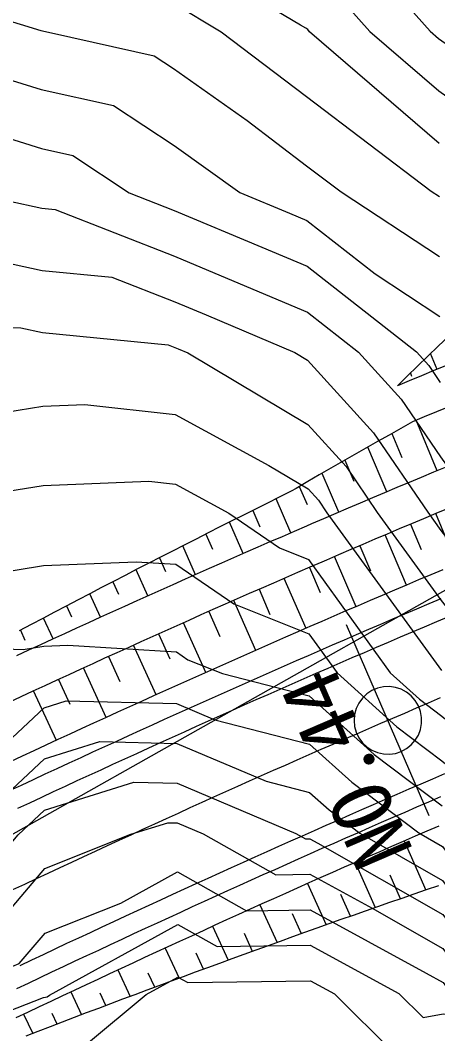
# Model space of a CAD drawing. Extents: x 42655 to 43811, y -141820 to -141156.
# Drawn here: x 43198.76 to 43214.79, y -141383.82 to -141344.87 of the extents above; entities that cross this region are included whole.
import ezdxf

# ---------------------------------------------------------------- set-up
doc = ezdxf.new("R2010")
doc.units = 0
for name, color, linetype in [('D-BMK-HTXT_1', 7, 'Continuous'), ('D-BMK_1', 7, 'Continuous'), ('D-STR-STR5_1', 7, 'Continuous'), ('D-STR_1', 7, 'Continuous'), ('ZE_HICN', 7, 'Continuous'), ('ZE_LWCN', 7, 'Continuous')]:
    doc.layers.add(name, color=color, linetype=linetype)

msp = doc.modelspace()

# ---------------------------------------------------------------- linework, layer by layer
at = {"layer": 'D-BMK-HTXT_1'}
for p, q in [((43274.802, -141333.044), (43130.975, -141414.265)), ((43214.46, -141375.449), (43211.289, -141368.104))]:
    msp.add_line(p, q, dxfattribs=at)
msp.add_lwpolyline([(43211.575, -141371.776), (43211.595, -141372.008), (43211.657, -141372.233), (43211.759, -141372.443), (43211.896, -141372.632), (43212.064, -141372.793), (43212.259, -141372.921), (43212.473, -141373.013), (43212.7, -141373.065), (43212.933, -141373.075), (43213.164, -141373.044), (43213.385, -141372.972), (43213.591, -141372.861), (43213.773, -141372.716), (43213.926, -141372.54), (43214.046, -141372.34), (43214.128, -141372.122), (43214.169, -141371.893), (43214.169, -141371.66), (43214.128, -141371.43), (43214.046, -141371.212), (43213.926, -141371.012), (43213.773, -141370.837), (43213.591, -141370.691), (43213.385, -141370.581), (43213.164, -141370.509), (43212.933, -141370.478), (43212.7, -141370.488), (43212.473, -141370.54), (43212.259, -141370.632), (43212.064, -141370.76), (43211.896, -141370.921), (43211.759, -141371.11), (43211.657, -141371.319), (43211.595, -141371.544), (43211.575, -141371.776)], dxfattribs=at)
at = {"layer": 'D-BMK_1'}
msp.add_lwpolyline([(43214.886, -141370.914), (43214.426, -141371.11), (43213.966, -141371.307), (43213.507, -141371.504), (43213.048, -141371.702), (43212.589, -141371.9), (43212.13, -141372.099), (43211.671, -141372.298), (43211.213, -141372.498), (43210.755, -141372.698), (43210.297, -141372.899), (43209.839, -141373.1), (43209.382, -141373.302), (43208.925, -141373.505), (43208.468, -141373.707), (43208.011, -141373.911), (43207.554, -141374.115), (43207.098, -141374.319), (43206.642, -141374.524), (43206.186, -141374.729), (43205.73, -141374.935), (43205.275, -141375.141), (43204.82, -141375.348), (43204.365, -141375.556), (43203.91, -141375.763), (43203.455, -141375.971), (43203.001, -141376.18), (43202.547, -141376.389), (43202.093, -141376.599), (43201.639, -141376.809), (43201.185, -141377.019), (43200.732, -141377.23), (43200.279, -141377.442), (43199.826, -141377.654), (43199.373, -141377.866), (43198.921, -141378.079), (43198.469, -141378.292)], dxfattribs=at)
at = {"layer": 'D-STR-STR5_1'}
for p, q in [((43214.761, -141358.286), (43214.511, -141357.68)), ((43213.738, -141358.431), (43213.787, -141358.55)), ((43214.765, -141362.181), (43213.958, -141360.243)), ((43213.026, -141360.749), (43213.411, -141361.668)), ((43212.829, -141362.994), (43212.103, -141361.275)), ((43211.225, -141361.777), (43211.567, -141362.581)), ((43210.989, -141363.777), (43210.349, -141362.281)), ((43209.474, -141362.787), (43209.772, -141363.479)), ((43209.152, -141364.568), (43208.583, -141363.257)), ((43207.685, -141363.707), (43207.96, -141364.337)), ((43215.526, -141365.765), (43214.715, -141363.828)), ((43207.319, -141365.367), (43206.788, -141364.158)), ((43213.743, -141364.236), (43214.15, -141365.204)), ((43205.892, -141364.612), (43206.148, -141365.191)), ((43213.591, -141366.581), (43212.771, -141364.648)), ((43205.489, -141366.175), (43204.997, -141365.068)), ((43211.8, -141365.061), (43212.213, -141366.027)), ((43204.104, -141365.525), (43204.339, -141366.054)), ((43211.66, -141367.406), (43210.83, -141365.477)), ((43209.862, -141365.895), (43210.279, -141366.859)), ((43203.663, -141366.99), (43203.211, -141365.985)), ((43209.733, -141368.241), (43208.894, -141366.316)), ((43202.32, -141366.446), (43202.535, -141366.924)), ((43201.84, -141367.814), (43201.429, -141366.909)), ((43207.928, -141366.738), (43208.349, -141367.7)), ((43200.54, -141367.374), (43200.735, -141367.801)), ((43207.81, -141369.084), (43206.962, -141367.163)), ((43200.021, -141368.644), (43199.652, -141367.841)), ((43205.998, -141367.59), (43206.424, -141368.55)), ((43205.891, -141369.937), (43205.034, -141368.02)), ((43198.765, -141368.309), (43198.938, -141368.686)), ((43204.072, -141368.451), (43204.502, -141369.409)), ((43203.976, -141370.798), (43203.11, -141368.885)), ((43202.15, -141369.32), (43202.585, -141370.276)), ((43202.064, -141371.668), (43201.191, -141369.758)), ((43200.232, -141370.198), (43200.671, -141371.152)), ((43200.157, -141372.546), (43199.275, -141370.64)), ((43213.504, -141376.407), (43214.326, -141378.296)), ((43211.617, -141377.233), (43212.384, -141378.972)), ((43213.355, -141378.633), (43212.958, -141377.726)), ((43209.789, -141378.044), (43210.5, -141379.637)), ((43211.441, -141379.303), (43211.072, -141378.471)), ((43207.964, -141378.863), (43208.618, -141380.311)), ((43209.558, -141379.973), (43209.217, -141379.213)), ((43206.143, -141379.689), (43206.738, -141380.993)), ((43207.678, -141380.651), (43207.365, -141379.963)), ((43204.325, -141380.523), (43204.861, -141381.684)), ((43205.799, -141381.338), (43205.516, -141380.721)), ((43202.511, -141381.365), (43202.985, -141382.382)), ((43203.923, -141382.032), (43203.67, -141381.488)), ((43200.7, -141382.213), (43201.112, -141383.089)), ((43202.049, -141382.735), (43201.827, -141382.261)), ((43198.892, -141383.069), (43199.241, -141383.803)), ((43200.176, -141383.445), (43199.986, -141383.042))]:
    msp.add_line(p, q, dxfattribs=at)
for points in [[(43221.944, -141353.148), (43221.489, -141353.403), (43221.035, -141353.659), (43220.581, -141353.915), (43220.127, -141354.172), (43219.673, -141354.429), (43219.22, -141354.687), (43218.768, -141354.945), (43218.316, -141355.204), (43217.864, -141355.464), (43217.413, -141355.724), (43216.962, -141355.984), (43216.511, -141356.245), (43216.061, -141356.507), (43215.611, -141356.769), (43215.209, -141357.004), (43214.811, -141357.389), (43214.413, -141357.775), (43214.016, -141358.161), (43213.619, -141358.547), (43213.242, -141358.916)], [(43215.594, -141357.943), (43215.119, -141358.138), (43214.644, -141358.334), (43214.169, -141358.531), (43213.694, -141358.728), (43213.242, -141358.916)], [(43215.216, -141359.721), (43214.743, -141359.916), (43214.27, -141360.113), (43213.82, -141360.3), (43213.371, -141360.554), (43212.923, -141360.808), (43212.475, -141361.063), (43212.027, -141361.318), (43211.58, -141361.573), (43211.134, -141361.829), (43210.688, -141362.086), (43210.242, -141362.343), (43209.797, -141362.6), (43209.352, -141362.858), (43209.164, -141362.967), (43208.706, -141363.195), (43208.249, -141363.424), (43207.792, -141363.653), (43207.336, -141363.882), (43206.88, -141364.112), (43206.424, -141364.342), (43205.969, -141364.573), (43205.513, -141364.805), (43205.059, -141365.037), (43204.604, -141365.269), (43204.15, -141365.502), (43203.696, -141365.735), (43203.243, -141365.968), (43202.79, -141366.203), (43202.337, -141366.437), (43201.884, -141366.672), (43201.432, -141366.908), (43200.98, -141367.144), (43200.529, -141367.38), (43200.078, -141367.617), (43199.627, -141367.854), (43199.176, -141368.091), (43198.726, -141368.329)], [(43215.076, -141362.052), (43214.628, -141362.239), (43214.158, -141362.435), (43213.689, -141362.632), (43213.219, -141362.829), (43212.75, -141363.027), (43212.281, -141363.226), (43211.813, -141363.425), (43211.345, -141363.624), (43210.877, -141363.824), (43210.409, -141364.025), (43209.942, -141364.226), (43209.744, -141364.312), (43209.277, -141364.513), (43208.811, -141364.716), (43208.344, -141364.919), (43207.878, -141365.122), (43207.412, -141365.326), (43206.947, -141365.531), (43206.481, -141365.736), (43206.016, -141365.941), (43205.552, -141366.147), (43205.087, -141366.354), (43204.623, -141366.561), (43204.159, -141366.768), (43203.695, -141366.976), (43203.232, -141367.184), (43202.769, -141367.393), (43202.306, -141367.602), (43201.843, -141367.812), (43201.381, -141368.022), (43200.919, -141368.233), (43200.457, -141368.444), (43199.995, -141368.656), (43199.534, -141368.868), (43199.073, -141369.081), (43198.612, -141369.294)], [(43215.184, -141363.632), (43214.716, -141363.828), (43214.248, -141364.024), (43213.78, -141364.221), (43213.313, -141364.418), (43212.846, -141364.616), (43212.379, -141364.814), (43211.912, -141365.013), (43211.446, -141365.212), (43210.98, -141365.412), (43210.514, -141365.613), (43210.339, -141365.689), (43209.874, -141365.89), (43209.408, -141366.092), (43208.944, -141366.294), (43208.479, -141366.497), (43208.015, -141366.7), (43207.551, -141366.904), (43207.087, -141367.108), (43206.623, -141367.313), (43206.16, -141367.518), (43205.697, -141367.724), (43205.234, -141367.93), (43204.772, -141368.137), (43204.31, -141368.344), (43203.848, -141368.552), (43203.386, -141368.76), (43202.924, -141368.969), (43202.463, -141369.178), (43202.002, -141369.388), (43201.542, -141369.598), (43201.081, -141369.808), (43200.621, -141370.019), (43200.161, -141370.231), (43199.701, -141370.443), (43199.242, -141370.655), (43198.783, -141370.868), (43198.324, -141371.081)], [(43214.812, -141378.129), (43214.344, -141378.29), (43213.877, -141378.451), (43213.41, -141378.614), (43212.942, -141378.777), (43212.475, -141378.94), (43212.008, -141379.104), (43211.541, -141379.268), (43211.074, -141379.433), (43210.608, -141379.599), (43210.141, -141379.765), (43209.675, -141379.932), (43209.208, -141380.099), (43208.742, -141380.266), (43208.276, -141380.435), (43207.81, -141380.603), (43207.344, -141380.773), (43206.878, -141380.942), (43206.412, -141381.113), (43205.947, -141381.283), (43205.481, -141381.455), (43205.016, -141381.627), (43204.55, -141381.799), (43204.085, -141381.972), (43203.62, -141382.145), (43203.155, -141382.319), (43202.69, -141382.493), (43202.226, -141382.668), (43201.761, -141382.843), (43201.296, -141383.019), (43200.832, -141383.195), (43200.368, -141383.372), (43199.904, -141383.549), (43199.439, -141383.727), (43198.975, -141383.905)]]:
    msp.add_lwpolyline(points, dxfattribs=at)
at = {"layer": 'D-STR_1'}
for points in [[(43214.985, -141365.986), (43214.519, -141366.182), (43214.054, -141366.379), (43213.588, -141366.576), (43213.123, -141366.773), (43212.659, -141366.972), (43212.194, -141367.17), (43211.73, -141367.37), (43211.266, -141367.569), (43210.802, -141367.77), (43210.338, -141367.971), (43209.875, -141368.172), (43209.412, -141368.374), (43208.949, -141368.576), (43208.487, -141368.779), (43208.025, -141368.982), (43207.563, -141369.186), (43207.101, -141369.391), (43206.639, -141369.596), (43206.178, -141369.801), (43205.717, -141370.007), (43205.256, -141370.213), (43204.796, -141370.42), (43204.336, -141370.627), (43203.876, -141370.835), (43203.416, -141371.043), (43202.956, -141371.252), (43202.497, -141371.461), (43202.038, -141371.671), (43201.579, -141371.881), (43201.121, -141372.092), (43200.662, -141372.303), (43200.204, -141372.514), (43199.746, -141372.726), (43199.289, -141372.939), (43198.832, -141373.151), (43198.375, -141373.365)], [(43214.908, -141367.104), (43214.443, -141367.3), (43213.979, -141367.496), (43213.515, -141367.694), (43213.051, -141367.891), (43212.588, -141368.09), (43212.125, -141368.288), (43211.662, -141368.488), (43211.199, -141368.688), (43210.736, -141368.888), (43210.274, -141369.089), (43209.812, -141369.29), (43209.351, -141369.492), (43208.889, -141369.695), (43208.428, -141369.897), (43207.967, -141370.101), (43207.506, -141370.305), (43207.046, -141370.509), (43206.585, -141370.714), (43206.125, -141370.92), (43205.666, -141371.126), (43205.206, -141371.332), (43204.747, -141371.539), (43204.288, -141371.746), (43203.829, -141371.954), (43203.37, -141372.162), (43202.912, -141372.371), (43202.454, -141372.58), (43201.996, -141372.79), (43201.538, -141373), (43201.081, -141373.211), (43200.624, -141373.422), (43200.167, -141373.634), (43199.71, -141373.846), (43199.254, -141374.058), (43198.798, -141374.271), (43198.342, -141374.484)], [(43215.199, -141367.795), (43214.735, -141367.991), (43214.272, -141368.187), (43213.809, -141368.384), (43213.346, -141368.581), (43212.883, -141368.779), (43212.421, -141368.977), (43211.959, -141369.176), (43211.497, -141369.376), (43211.035, -141369.576), (43210.574, -141369.776), (43210.112, -141369.978), (43209.651, -141370.179), (43209.191, -141370.381), (43208.73, -141370.584), (43208.27, -141370.787), (43207.81, -141370.991), (43207.35, -141371.195), (43206.891, -141371.399), (43206.432, -141371.604), (43205.973, -141371.81), (43205.514, -141372.016), (43205.055, -141372.223), (43204.597, -141372.43), (43204.139, -141372.637), (43203.681, -141372.845), (43203.223, -141373.054), (43202.766, -141373.262), (43202.309, -141373.472), (43201.852, -141373.682), (43201.395, -141373.892), (43200.939, -141374.103), (43200.482, -141374.314), (43200.026, -141374.526), (43199.571, -141374.738), (43199.115, -141374.95), (43198.66, -141375.163)], [(43215.049, -141373.834), (43214.593, -141374.03), (43214.136, -141374.227), (43213.68, -141374.424), (43213.224, -141374.621), (43212.769, -141374.819), (43212.313, -141375.018), (43211.858, -141375.217), (43211.403, -141375.417), (43210.948, -141375.617), (43210.493, -141375.817), (43210.039, -141376.019), (43209.585, -141376.22), (43209.131, -141376.422), (43208.677, -141376.625), (43208.223, -141376.828), (43207.77, -141377.032), (43207.317, -141377.236), (43206.864, -141377.441), (43206.411, -141377.646), (43205.958, -141377.851), (43205.506, -141378.058), (43205.054, -141378.264), (43204.602, -141378.471), (43204.15, -141378.679), (43203.698, -141378.887), (43203.247, -141379.095), (43202.796, -141379.304), (43202.345, -141379.513), (43201.894, -141379.723), (43201.443, -141379.933), (43200.993, -141380.144), (43200.542, -141380.355), (43200.092, -141380.567), (43199.642, -141380.779), (43199.193, -141380.991), (43198.743, -141381.204)], [(43214.889, -141374.719), (43214.433, -141374.916), (43213.978, -141375.112), (43213.523, -141375.309), (43213.068, -141375.507), (43212.613, -141375.705), (43212.159, -141375.904), (43211.705, -141376.103), (43211.251, -141376.303), (43210.797, -141376.503), (43210.343, -141376.704), (43209.89, -141376.906), (43209.436, -141377.107), (43208.983, -141377.31), (43208.53, -141377.513), (43208.078, -141377.716), (43207.625, -141377.92), (43207.173, -141378.124), (43206.721, -141378.329), (43206.269, -141378.534), (43205.817, -141378.74), (43205.366, -141378.946), (43204.914, -141379.153), (43204.463, -141379.36), (43204.012, -141379.568), (43203.562, -141379.776), (43203.111, -141379.984), (43202.661, -141380.193), (43202.21, -141380.403), (43201.76, -141380.613), (43201.311, -141380.823), (43200.861, -141381.034), (43200.412, -141381.245), (43199.962, -141381.457), (43199.513, -141381.669), (43199.064, -141381.882), (43198.616, -141382.095)], [(43214.829, -141375.834), (43214.375, -141376.03), (43213.921, -141376.227), (43213.467, -141376.424), (43213.014, -141376.622), (43212.56, -141376.82), (43212.107, -141377.019), (43211.654, -141377.218), (43211.201, -141377.418), (43210.748, -141377.618), (43210.296, -141377.819), (43209.844, -141378.021), (43209.391, -141378.223), (43208.94, -141378.425), (43208.488, -141378.628), (43208.036, -141378.831), (43207.585, -141379.035), (43207.134, -141379.24), (43206.683, -141379.444), (43206.232, -141379.65), (43205.782, -141379.856), (43205.331, -141380.062), (43204.881, -141380.269), (43204.431, -141380.476), (43203.981, -141380.683), (43203.532, -141380.892), (43203.082, -141381.1), (43202.633, -141381.309), (43202.184, -141381.519), (43201.735, -141381.729), (43201.286, -141381.939), (43200.837, -141382.15), (43200.389, -141382.362), (43199.941, -141382.573), (43199.493, -141382.786), (43199.045, -141382.998), (43198.597, -141383.211)]]:
    msp.add_lwpolyline(points, dxfattribs=at)
at = {"layer": 'ZE_HICN'}
for points in [[(43212.022, -141342.507), (43214.496, -141345.285), (43214.821, -141345.567), (43217.891, -141347.727), (43219.932, -141350.454), (43220.465, -141351.42), (43222.491, -141354.497), (43225.051, -141356.906), (43225.628, -141356.859), (43225.848, -141357.557), (43230.163, -141362.035), (43234.041, -141357.519), (43234.338, -141356.443), (43234.694, -141351.353), (43235.175, -141345.716), (43235.233, -141345.261), (43235.243, -141345.188), (43235.33, -141344.995), (43238.368, -141339.01)], [(43195.104, -141346.143), (43199.566, -141347.531), (43202.342, -141348.147), (43204.664, -141349.687), (43207.196, -141351.482), (43209.099, -141352.28), (43209.766, -141352.562), (43212.383, -141354.616), (43214.872, -141356.252)], [(43197.717, -141360.001), (43199.623, -141359.694), (43201.238, -141359.629), (43204.713, -141360.015), (43208.304, -141361.978), (43209.815, -141362.88), (43210.211, -141363.317), (43210.535, -141363.792), (43214.936, -141369.853)], [(43196.563, -141376.183), (43199.687, -141373.255), (43201.82, -141372.583), (43204.772, -141372.658), (43208.204, -141374.114), (43209.869, -141374.543), (43210.616, -141375.217), (43211.799, -141376.112), (43214.974, -141377.928), (43218.16, -141382.244), (43220.088, -141383.408), (43221.161, -141383.53), (43225.171, -141382.371), (43227.652, -141382.2), (43230.023, -141381.905), (43230.257, -141382.055), (43230.434, -141381.972), (43235.342, -141381.268), (43239.267, -141380.739), (43240.422, -141379.634), (43242.786, -141379.264)], [(43201.304, -141384.22), (43203.592, -141382.313), (43204.815, -141381.64), (43205.19, -141381.851), (43209.904, -141381.779), (43210.82, -141382.279), (43213.111, -141384.562)]]:
    msp.add_lwpolyline(points, dxfattribs=at)
at = {"layer": 'ZE_LWCN'}
for points in [[(43210.911, -141343.867), (43212.183, -141345.296), (43214.831, -141347.587), (43216.845, -141349.005), (43218.66, -141351.429), (43219.944, -141352.862), (43221.677, -141355.493), (43223.88, -141357.567), (43225.062, -141359.213), (43229.503, -141363.703), (43229.876, -141364.06), (43230.173, -141364.139), (43230.403, -141363.978), (43230.973, -141363.696), (43235.236, -141358.863), (43235.657, -141358.025), (43235.9, -141357.51), (43236.274, -141356.237), (43236.788, -141351.343), (43237.255, -141347.687), (43237.621, -141345.177), (43240.233, -141339.367)], [(43214.84, -141349.608), (43209.871, -141345.307), (43209.799, -141345.226), (43209.731, -141345.177), (43209.526, -141345.061), (43204.629, -141342.146)], [(43195.574, -141344.027), (43199.555, -141345.265), (43199.955, -141345.354), (43203.908, -141346.232), (43204.65, -141346.724), (43207.473, -141348.726), (43209.756, -141350.461), (43211.076, -141351.464), (43214.861, -141353.953)], [(43214.85, -141351.653), (43214.537, -141351.448), (43209.744, -141347.805), (43206.478, -141345.323), (43204.639, -141344.228)], [(43197.65, -141349.197), (43199.577, -141349.796), (43200.775, -141350.063), (43202.947, -141351.502), (43204.676, -141352.179), (43208.032, -141353.585), (43209.774, -141354.323), (43213.967, -141357.613), (43214.444, -141358.14), (43214.883, -141358.784)], [(43196.987, -141351.531), (43199.588, -141352.092), (43200.105, -141352.143), (43204.684, -141353.935), (43206.965, -141354.89), (43209.783, -141356.084), (43211.745, -141357.624), (43213.386, -141359.434), (43214.897, -141361.651), (43215.714, -141362.785), (43216.214, -141363.765), (43220.018, -141368.578), (43220.637, -141369.161), (43221.28, -141369.904), (43225.122, -141371.925), (43228.71, -141376.032), (43230.234, -141377.004), (43232.343, -141376.015), (43235.294, -141371.025), (43235.731, -141370.369), (43236.688, -141369.832), (43240.363, -141367.073), (43242.073, -141365.722)], [(43196.364, -141353.782), (43199.599, -141354.48), (43202.273, -141354.744), (43204.693, -141355.691), (43205.897, -141356.195), (43209.298, -141357.635), (43209.791, -141357.93), (43212.327, -141360.728), (43214.404, -141363.774), (43214.91, -141364.471), (43219.169, -141369.914), (43219.679, -141370.332), (43220.032, -141371.595), (43220.712, -141370.735), (43225.127, -141373.058), (43227.729, -141376.037), (43230.237, -141377.635), (43233.707, -141376.008), (43235.304, -141373.308), (43236.582, -141371.391), (43239.38, -141369.819), (43240.373, -141369.074), (43243.082, -141366.933)], [(43194.52, -141356.569), (43198.789, -141356.692), (43199.61, -141356.869), (43204.442, -141357.345), (43204.701, -141357.446), (43204.83, -141357.5), (43205.194, -141357.655), (43209.803, -141360.405), (43211.269, -141362.022), (43212.469, -141363.783), (43214.923, -141367.162), (43217.084, -141369.924), (43218.837, -141371.362), (43220.051, -141375.703), (43222.39, -141372.748), (43225.132, -141374.191), (43226.749, -141376.041), (43230.24, -141378.266), (43235.072, -141376.002), (43235.315, -141375.59), (43237.434, -141372.412), (43240.381, -141370.757), (43241.987, -141369.807)], [(43194.842, -141363.516), (43199.638, -141362.745), (43203.698, -141362.58), (43204.726, -141362.694), (43206.766, -141363.81), (43208.712, -141365.149), (43209.827, -141365.593), (43212.962, -141369.943), (43214.093, -141370.965), (43214.944, -141371.609), (43217.154, -141373.42), (43217.898, -141376.083), (43220.067, -141379.091), (43224.366, -141376.996), (43225.144, -141376.582), (43225.544, -141376.532), (43230.246, -141379.529), (43233.79, -141377.868), (43235.325, -141377.648), (43236.552, -141377.483), (43238.115, -141375.988), (43239.137, -141374.455), (43240.395, -141373.748), (43243.944, -141371.649)], [(43196.602, -141366.323), (43199.652, -141365.825), (43203.211, -141365.679), (43204.74, -141365.773), (43206.956, -141367.297), (43209.841, -141368.446), (43210.927, -141369.953), (43213.224, -141372.028), (43214.952, -141373.335), (43216.312, -141374.45), (43216.77, -141376.088), (43220.075, -141380.671), (43222.213, -141379.629), (43225.151, -141378.063), (43226.664, -141377.876), (43230.249, -141380.161), (43232.951, -141378.894), (43235.329, -141378.553), (43237.231, -141378.297), (43239.652, -141375.98), (43239.988, -141375.476), (43240.402, -141375.244), (43241.569, -141374.554), (43245.482, -141373.59)], [(43194.578, -141368.893), (43198.876, -141369.051), (43199.667, -141368.922), (43200.589, -141368.884), (43204.756, -141369.14), (43205.199, -141369.445), (43206.527, -141369.974), (43209.852, -141370.83), (43212.354, -141373.091), (43214.96, -141375.061)], [(43195.167, -141375.514), (43199.678, -141371.286), (43200.518, -141371.021), (43204.765, -141371.129), (43206.236, -141371.753), (43209.861, -141372.687), (43211.485, -141374.154), (43214.06, -141376.101), (43214.967, -141376.62), (43219.116, -141382.24), (43220.085, -141382.825), (43220.624, -141382.886), (43222.921, -141382.222), (43225.164, -141381.026), (43228.903, -141380.562), (43230.254, -141381.423), (43231.273, -141380.946), (43235.338, -141380.363), (43238.588, -141379.925), (43240.416, -141378.177), (43244.153, -141377.592)], [(43174.24, -141371.841), (43176.495, -141373.556), (43178.494, -141376.268), (43179.352, -141376.917), (43182.381, -141378.753), (43184.45, -141379.169), (43186.858, -141379.478), (43189.543, -141380.192), (43192.853, -141380.209), (43194.628, -141379.443), (43196.626, -141378.608), (43198.683, -141376.173), (43199.696, -141375.223), (43203.122, -141374.145), (43204.78, -141374.187), (43209.343, -141376.123), (43209.708, -141376.328), (43209.878, -141376.325), (43210.189, -141376.495), (43214.98, -141379.237), (43217.203, -141382.249), (43220.09, -141383.992)], [(43174.249, -141373.835), (43175.493, -141374.781), (43176.596, -141376.277), (43179.359, -141378.367), (43181.591, -141379.72), (43184.456, -141380.296), (43186.024, -141380.497), (43189.549, -141381.435), (43193.893, -141381.457), (43194.636, -141381.136), (43197.675, -141379.865), (43199.707, -141377.461), (43203.008, -141376.153), (43204.424, -141375.707), (43204.787, -141375.716), (43205.785, -141376.14), (43208.578, -141377.709), (43209.884, -141377.689), (43212.269, -141378.99), (43214.986, -141380.545), (43216.247, -141382.253), (43220.093, -141384.575)], [(43174.697, -141376.286), (43179.365, -141379.817), (43180.8, -141380.687), (43184.461, -141381.423), (43185.191, -141381.516), (43188.454, -141382.384), (43189.556, -141382.773), (43194.268, -141382.812), (43194.644, -141382.799), (43195.791, -141382.35), (43198.723, -141381.123), (43199.719, -141379.946), (43202.621, -141378.796), (43204.796, -141377.599), (43207.449, -141379.09), (43209.891, -141379.052), (43214.349, -141381.486), (43214.992, -141381.854), (43215.29, -141382.258), (43220.096, -141385.159)], [(43194.651, -141384.383), (43199.653, -141382.424), (43199.73, -141382.415), (43199.79, -141382.404), (43199.878, -141382.33), (43204.805, -141379.62), (43206.32, -141380.47), (43209.897, -141380.415), (43213.29, -141382.267), (43214.225, -141383.199), (43214.998, -141383.054), (43215.668, -141383.068), (43220.098, -141385.743)]]:
    msp.add_lwpolyline(points, dxfattribs=at)

# ---------------------------------------------------------------- texts
at = {"layer": 'D-BMK-HTXT_1'}
msp.add_text('NO.44', height=2.3065, rotation=113.3503, dxfattribs=at).set_placement((43213.869, -141376.793))

doc.saveas('drawing.dxf')
